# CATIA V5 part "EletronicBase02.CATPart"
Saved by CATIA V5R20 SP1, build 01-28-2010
Part number: BaseEletronic
Bounding box of the stored display mesh (mm): x 0 to 151.142, y 0 to 93, z 0 to 26
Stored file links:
  C:\Users\elisf\Desktop\Elis\ENSINOFATEC\MAV5\DIP\Labirinto\RealBox\EletronicBase02.CATPart
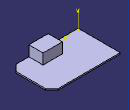
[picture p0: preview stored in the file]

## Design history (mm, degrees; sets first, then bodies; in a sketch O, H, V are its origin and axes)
Body1 (main body)
  Sketch1 on xy-plane, origin (0, 0, 0), H (1, 0, 0), V (0, 1, 0)
    line L1 (0, 0) -> (137, 0)
    line L2 (137, 0) -> (151.1421, 14.1421)
    line L3 (151.1421, 14.1421) -> (151.1421, 78.8579)
    line L4 (151.1421, 78.8579) -> (137, 93)
    line L5 (137, 93) -> (0, 93)
    point P5 (0, 93)
    line L6 (0, 93) -> (0, 0)
    construction line L7 (0, 46.5) -> (60.8498, 46.5)
    point P6 (0, 46.5)
    length L2 = 20
    length L4 = 20
    length L6 = 93
    angle L2 L1 = 135
    angle L4 L5 = 135
    length L1 = 137
    horizontal: L1 H, L5 H, L7 H
    vertical: L3 V, L6 V
    coincidence: P5 V
    midpoint: P6 L6
    symmetry: L1 L5 L7
  Pad1: profile Sketch1, direction (0, 0, 1), length 3
  Sketch2 on end face of Pad1, origin (0, 0, 3), H (1, 0, 0), V (0, 1, 0)
    reference projected line E1 (0, 0) -> (137, 0) from edge [face of Pad1 from Sketch1.L1 | end face of Pad1]
    point P3 (66.2651, 0)
    line L1 (66.2651, 0) -> (108.9968, 0)
    line L2 (108.9968, 0) -> (108.9968, 31.3371)
    line L3 (108.9968, 31.3371) -> (66.2651, 31.3371)
    line L4 (66.2651, 31.3371) -> (66.2651, 0)
    coincidence: P3 E1
    horizontal: L1 H, L3 H
    vertical: L2 V, L4 V
  Pad2: profile Sketch2, direction (0, 0, 1), length 23
  Sketch3 on face of Pad2, origin (0, 0, 0), H (1, 0, 0), V (0, 0, 1)
    reference projected line E1 (66.2651, 26) -> (108.9968, 26) from edge [face of Pad2 | end face of Pad2]
    reference projected line E2 (0, 0) -> (137, 0) from edge [start face of Pad1 | face of Pad2]
    distance E1 E2 = 26 (reference)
